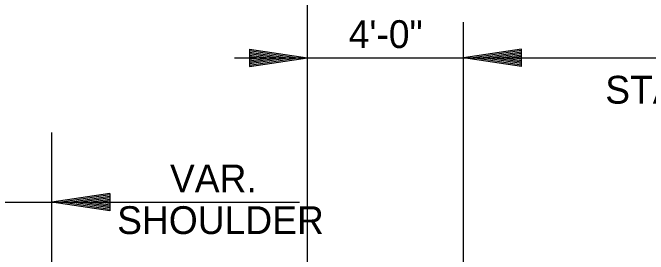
# Model space of a CAD drawing. Extents: x 1807779 to 1818251, y 673292 to 678849.
# Drawn here: x 1813411.4 to 1813575.9, y 677066.1 to 677128.6 of the extents above; entities that cross this region are included whole.
import ezdxf

# ---------------------------------------------------------------- set-up
doc = ezdxf.new("R2010")
doc.units = 0
doc.layers.add('Dimensions', color=7, linetype='Continuous')

msp = doc.modelspace()

# ---------------------------------------------------------------- linework, layer by layer
at = {"layer": 'Dimensions'}
for p, q in [((1813487.67, 676984.76), (1813487.67, 677242.53)), ((1813528.05, 676984.76), (1813528.05, 677126.17)), ((1813472.67, 677119.2), (1813487.67, 677116.95)), ((1813472.67, 677119.2), (1813472.67, 677114.7)), ((1813472.67, 677118.82), (1813485.17, 677116.95)), ((1813543.05, 677119.2), (1813528.05, 677116.95)), ((1813543.05, 677118.82), (1813530.56, 677116.95)), ((1813543.05, 677114.7), (1813543.05, 677119.2)), ((1813472.67, 677118.44), (1813482.59, 677116.95)), ((1813472.67, 677118.07), (1813480.09, 677116.95)), ((1813472.67, 677117.68), (1813477.55, 677116.95)), ((1813472.67, 677117.3), (1813475.04, 677116.95)), ((1813543.05, 677118.44), (1813533.14, 677116.95)), ((1813543.05, 677118.07), (1813535.64, 677116.95)), ((1813543.05, 677117.68), (1813538.18, 677116.95)), ((1813543.05, 677117.3), (1813540.68, 677116.95)), ((1813468.81, 677116.95), (1813528.05, 677116.95)), ((1813472.67, 677114.7), (1813487.67, 677116.95)), ((1813472.67, 677116.21), (1813477.55, 677116.95)), ((1813472.67, 677115.46), (1813482.59, 677116.95)), ((1813472.67, 677115.07), (1813485.17, 677116.95)), ((1813472.67, 677115.83), (1813480.09, 677116.95)), ((1813472.67, 677116.6), (1813475.04, 677116.95)), ((1813528.05, 677116.95), (1813678.05, 677116.95)), ((1813543.05, 677114.7), (1813528.05, 677116.95)), ((1813543.05, 677115.07), (1813530.56, 677116.95)), ((1813543.05, 677115.46), (1813533.14, 677116.95)), ((1813543.05, 677115.83), (1813535.64, 677116.95)), ((1813543.05, 677116.22), (1813538.18, 677116.95)), ((1813543.05, 677116.6), (1813540.68, 677116.95)), ((1813421.53, 676980.16), (1813421.53, 677097.63)), ((1813436.53, 677081.84), (1813421.53, 677079.59)), ((1813436.53, 677081.46), (1813424.04, 677079.59)), ((1813436.53, 677081.08), (1813426.62, 677079.59)), ((1813436.53, 677081.84), (1813436.53, 677077.34)), ((1813286.49, 677079.59), (1813485.64, 677079.59)), ((1813436.53, 677077.34), (1813421.53, 677079.59)), ((1813436.53, 677077.71), (1813424.04, 677079.59)), ((1813436.53, 677078.1), (1813426.62, 677079.59)), ((1813436.53, 677080.71), (1813429.11, 677079.59)), ((1813436.53, 677078.47), (1813429.11, 677079.59)), ((1813436.53, 677080.32), (1813431.66, 677079.59)), ((1813436.53, 677078.85), (1813431.66, 677079.59)), ((1813436.53, 677079.94), (1813434.16, 677079.59)), ((1813436.53, 677079.24), (1813434.16, 677079.59))]:
    msp.add_line(p, q, dxfattribs=at)

# ---------------------------------------------------------------- texts
for s, p in [('4\'-0"', (1813498.33, 677119.5)), ('STAGE 2 TRAFFIC', (1813564.74, 677105.1)), ('VAR.', (1813452.08, 677082.14)), ('SHOULDER', (1813438.41, 677071.34))]:
    msp.add_text(s, height=7.2, dxfattribs=at).set_placement(p)

doc.saveas('drawing.dxf')
